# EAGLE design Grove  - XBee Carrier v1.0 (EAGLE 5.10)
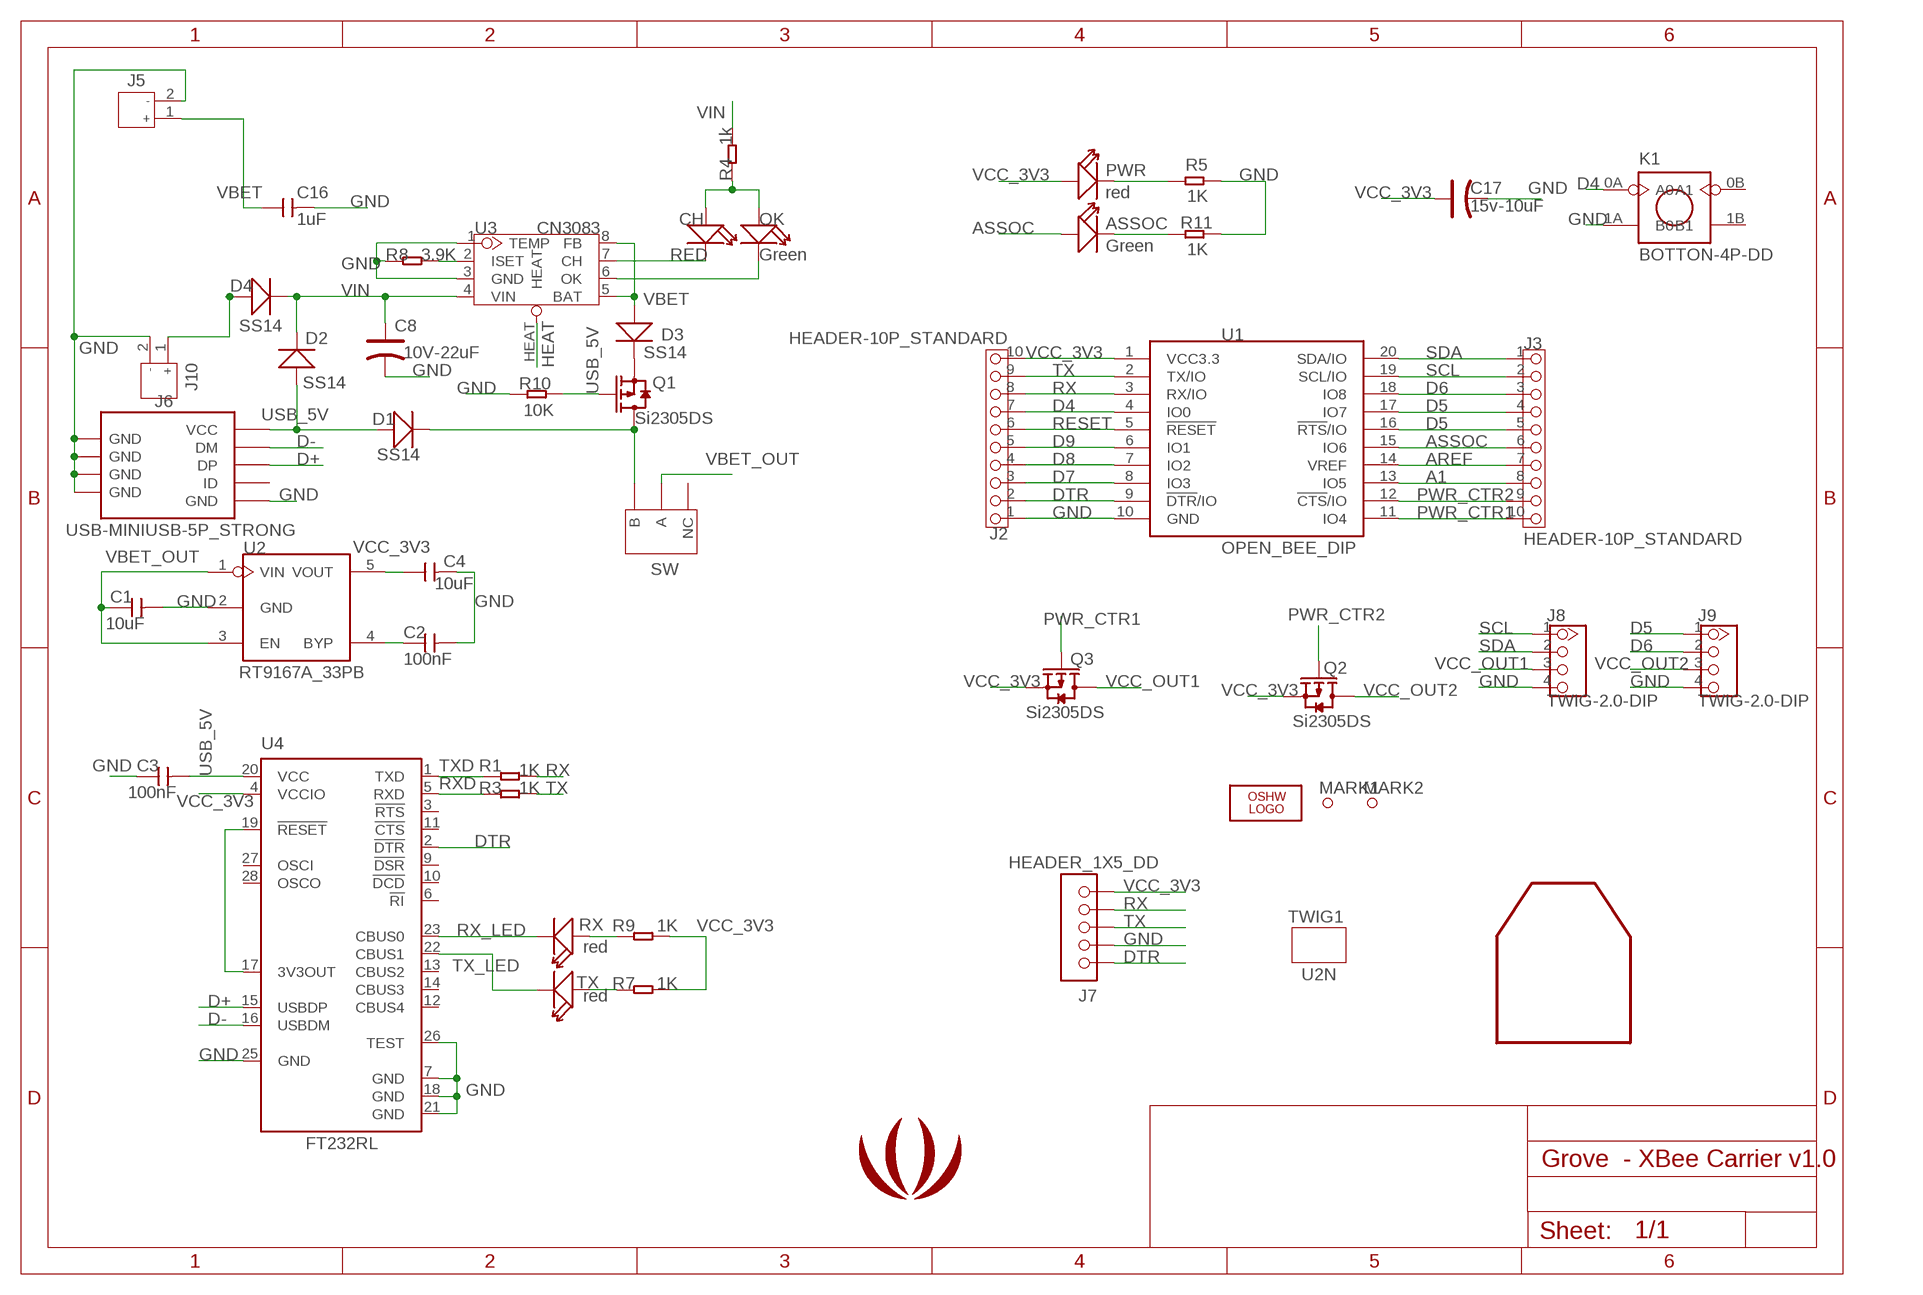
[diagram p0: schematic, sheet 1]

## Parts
ASSOC  Green  LED-0603  [D0603]
C1  10uF  C-0805  [0805]
C2  100nF  C-0603  [0603]
C3  100nF  C-0603  [0603]
C4  10uF  C-0805  [0805]
C8  10V-22uF  CAP_AVX_B  [AVX-B]
C16  1uF  C-0805  [0805]
C17  15v-10uF  CAP_AVX_A  [AVX-A]
CH  RED  LED-0603  [D0603]
D1  SS14  D-2010  [D2010]
D2  SS14  D-2010  [D2010]
D3  SS14  D-2010  [D2010]
D4  SS14  D-2010  [D2010]
J2  HEADER-10P_STANDARD  [2.54_10P]
J3  HEADER-10P_STANDARD  [2.54_10P]
J5  JST-2P-POWER-LEADED  [2P-2.0-LEADED-4.7X6.0]
J6  USB-MINIUSB-5P_STRONG  [MINI_STRONG]
J7  HEADER_1X5_DD  [CK_1X5]
J8  TWIG-2.0-DIP  [2.0_1X4]
J9  TWIG-2.0-DIP  [2.0_1X4]
J10  JST-2P-POWER-LEADED  [2P-2.0-LEADED-4.7X6.0]
K1  BOTTON-4P-DD  [BTN-S]
LOGO1  LOGO_SILK  [LOGO_SILK]
LOGO2  OSHW_LOGO_FILLX0200-NT  [OSHW_FILLX200_NOTEXT]
MARK1  PAD-MARK  [MARK]
MARK2  PAD-MARK  [MARK]
OK  Green  LED-0603  [D0603]
PWR  red  LED-0805  [D0805]
Q1  Si2305DS  010-P-MOSFETSOT23  [SOT23]
Q2  Si2305DS  010-P-MOSFETSOT23  [SOT23]
Q3  Si2305DS  010-P-MOSFETSOT23  [SOT23]
R1  1K  R-0603  [0603]
R3  1K  R-0603  [0603]
R4  1k  R-0603  [0603]
R5  1K  R-0603  [0603]
R7  1K  R-0603  [0603]
R8  3.9K  R-0603  [0603]
R9  1K  R-0603  [0603]
R10  10K  R-0603  [0603]
R11  1K  R-0603  [0603]
RX  red  LED-0603  [D0603]
SW  SWITCH-3P  [008-SW-3P-DIP]
TWIG1  U2N  [U2N_SILK]
TX  red  LED-0603  [D0603]
U1  OPEN_BEE_DIP  [CCBEE-PRO]
U2  RT9167A_33PB  RT9167A  [SOT23-5]
U3  CN3083  [SOP8]
U4  FT232RL  [SSOP28]
U$1  WIFI_SILK  [WIFI_SILK]

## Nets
A1: J3.8 U1.13(IO5)
AREF: J3.7 U1.14(VREF)
ASSOC: ASSOC.+ J3.6 U1.15(IO6)
D4: J2.7 K1.0A(A0) U1.4(IO0)
D5: J3.4 J3.5 J9.1 U1.16(!RTS!/IO) U1.17(IO7)
D6: J3.3 J9.2 U1.18(IO8)
D7: J2.3 U1.8(IO3)
D8: J2.4 U1.7(IO2)
D9: J2.5 U1.6(IO1)
D+: J6.3(DP) U4.15(USBDP)
D-: J6.2(DM) U4.16(USBDM)
DTR: J2.2 J7.1 U1.9(!DTR!/IO) U4.2(!DTR)
GND: C1.2 C2.2 C3.1 C4.2 C8.- C16.2 C17.- J2.1 J5.2 J6.5(GND) J6.GND@1(GND) J6.GND@2(GND) J6.GND@3(GND) J6.GND@4(GND) J7.2 J8.4 J9.4 J10.2 K1.1A(B0) R5.1 R8.1 R10.1 R11.1 U1.10(GND) U2.2(GND) U3.1(TEMP) U3.3(GND) U4.7(GND) U4.18(GND) U4.21(GND) U4.25(GND) U4.26(TEST)
HEAT: U3.HEAT
N$1: PWR.- R5.2
N$2: R8.2 U3.2(ISET)
N$3: D4.+ J10.1
N$6: C2.1 U2.4(BYP)
N$7: CH.- U3.7(CH)
N$8: OK.- U3.6(OK)
N$9: CH.+ OK.+ R4.1
N$10: U4.17(3V3OUT) U4.19(!RESET)
N$11: D3.- Q1.2(S)
N$12: ASSOC.- R11.2
N$13: D1.- Q1.3(D) SW.P$3(B)
N$15: R9.1 RX.+
N$16: R7.1 TX.+
PWR_CTR1: J3.10 Q3.1(G) U1.11(IO4)
PWR_CTR2: J3.9 Q2.1(G) U1.12(!CTS!/IO)
RESET: J2.6 U1.5(!RESET)
RX: J2.8 J7.4 R1.2 U1.3(RX/IO)
RX_LED: RX.- U4.23(CBUS0)
RXD: R3.1 U4.5(RXD)
SCL: J3.2 J8.1 U1.19(SCL/IO)
SDA: J3.1 J8.2 U1.20(SDA/IO)
TX: J2.9 J7.3 R3.2 U1.2(TX/IO)
TX_LED: TX.- U4.22(CBUS1)
TXD: R1.1 U4.1(TXD)
USB_5V: C3.2 D1.+ D2.+ J6.1(VCC) Q1.1(G) R10.2 U4.20(VCC)
VBET: C16.1 D3.+ J5.1 U3.5(BAT) U3.8(FB)
VBET_OUT: C1.1 SW.P$2(A) U2.1(VIN) U2.3(EN)
VCC_3V3: C4.1 C17.+ J2.10 J7.5 PWR.+ Q2.2(S) Q3.2(S) R7.2 R9.2 U1.1(VCC3.3) U2.5(VOUT) U4.4(VCCIO)
VCC_OUT1: J8.3 Q3.3(D)
VCC_OUT2: J9.3 Q2.3(D)
VIN: C8.+ D2.- D4.- R4.2 U3.4(VIN)
Unconnected: J6.4(ID) K1.0B(A1) K1.1B(B1) SW.P$1(NC) U4.3(!RTS) U4.6(!RI) U4.9(!DSR) U4.10(!DCD) U4.11(!CTS) U4.12(CBUS4) U4.13(CBUS2) U4.14(CBUS3) U4.27(OSCI) U4.28(OSCO)

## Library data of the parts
ASSOC CH OK PWR RX TX = Discrete:LED*
C1-C4 C16 = Discrete:C*: Ceramic Capacitors
C8 C17 = Discrete:CAP*: Electrolytic Capacitors,Tantalum Capacitors and Super Capacitors
D1-D4 = Discrete:D*
J2 J3 = Connector:HEADER-10P
J5 J10 = Connector:JST-2P-POWER-LEADED
J6 = Connector:USB-MINIUSB-5P
J7 = CONNECTER:HEADER_1X5
J8 J9 = Connector:TWIG-2.0-DIP
K1 = Discrete:BOTTON-4P
LOGO1 = logo:LOGO_SILK
LOGO2 = logo:OSHW_LOGO_FILL
MARK1 MARK2 = Discrete:PAD-MARK
Q1-Q3 = Discrete:010-P-MOSFET*: Si2305DS Si2323CDS
R1 R3-R5 R7-R11 = Discrete:R*
SW = Discrete:SWITCH-3P
TWIG1 = twig_template1:U2N
U1 = EXT_moudle:OPEN_BEE
U2 = IC:RT9167A: Voltage regulator
U3 = IC:CN3083
U4 = IC:FT232R: Source: http://www.ftdichip.com/Documents/DataSheets/DS_FT232R_v104.pdf
U$1 = seeedleo:WIFI_SILK

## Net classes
0 default: width 0.203 mm, drill 0.305 mm, clearance 0.127 mm

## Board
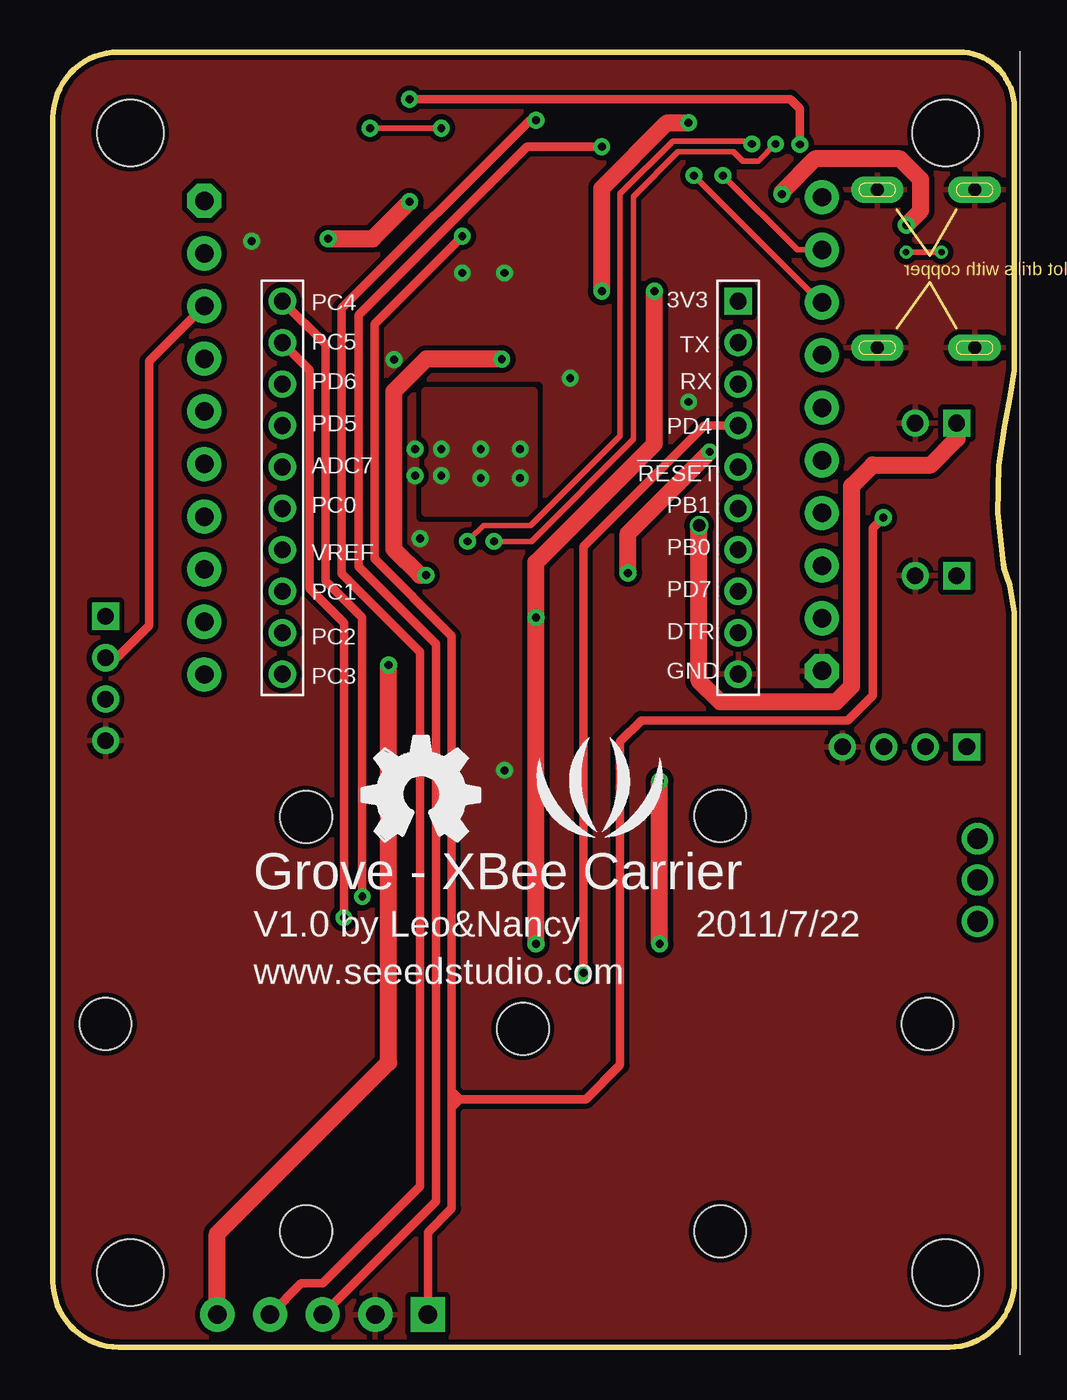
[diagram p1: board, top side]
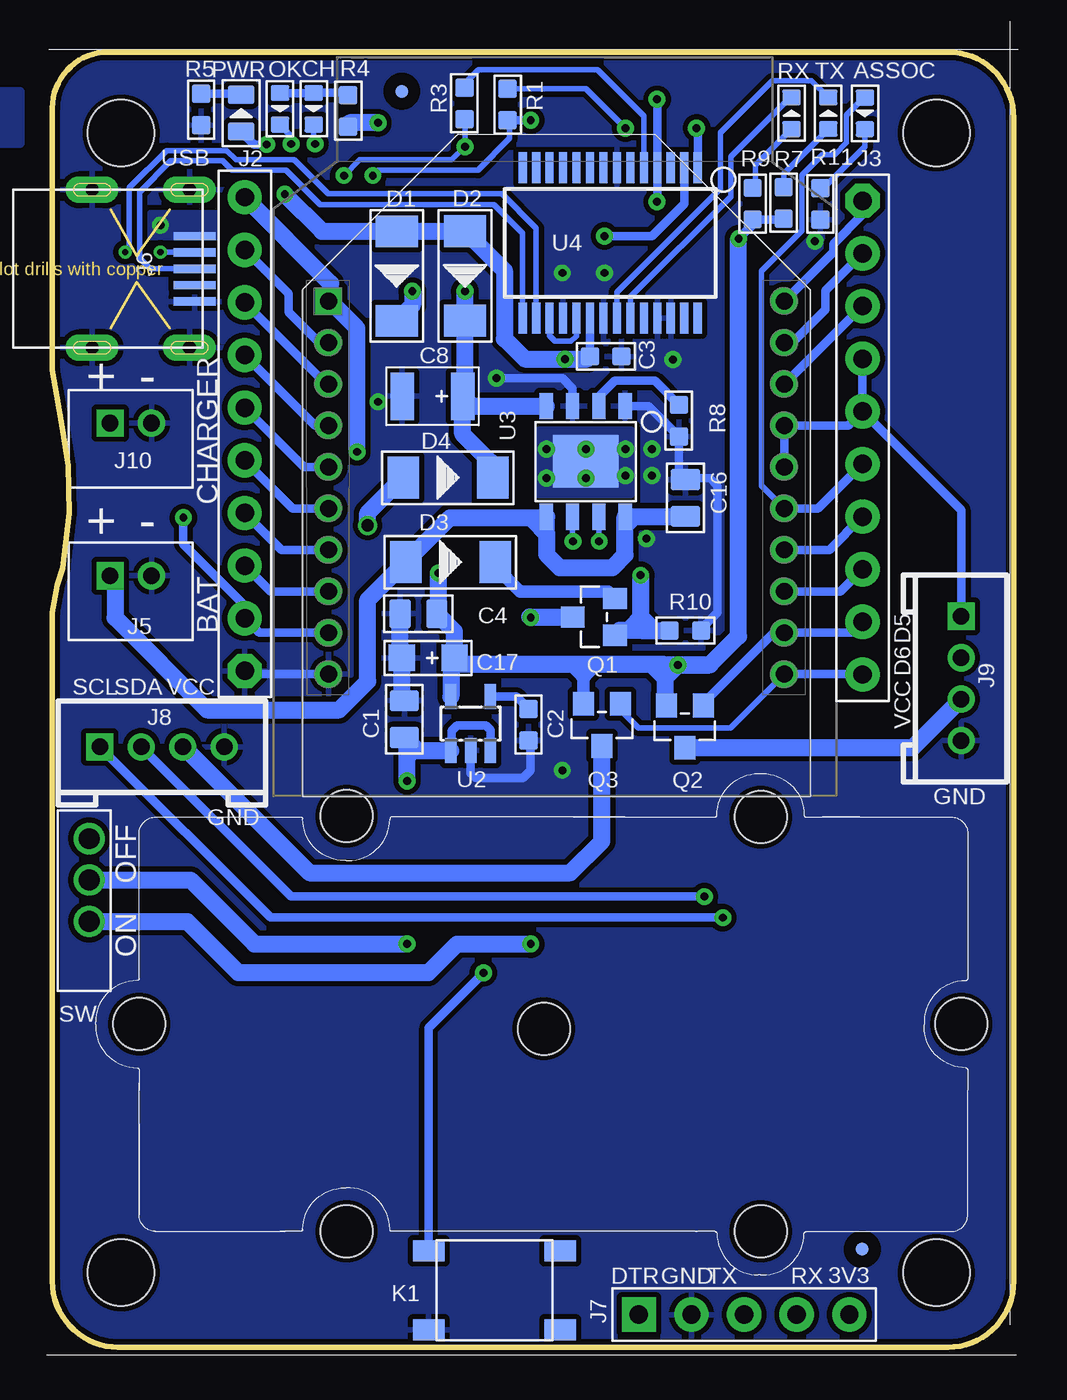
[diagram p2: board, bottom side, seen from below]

Size 46.48 x 62.53 mm. Coordinates in mm from the lower left corner, seen from the top.
Outline: 0,59.46 arc-67 2.69,62.53
Outline: 46.48,3.07 arc-67 43.79,0
Outline: 3.1,0 arc-67 0.03,2.69
Outline: 46.46,47.17 46.38,46.94
Outline: 46,38.05 46.46,35.46 46.46,3.2 arc-90 43.28,0.03 3.23,0.03 arc-90 0.06,3.2 0.06,59.35 arc-90 3.23,62.53 43.75,62.53 arc-90 46.46,59.82 46.46,47.17
Outline: 46.46,35.48 46.23,36.8 45.95,37.62 45.64,40.28 45.7,42.57 45.97,44.4 46.25,45.95 46.46,47.17
Copper layers (1*16): Top 0.035mm / dielectric 1.5mm / Bottom 0.035mm
Design rules "SeeedStudio_rule_no_angle_090911 *": minimum track width 6mil, minimum drill 12mil, track to track 6mil, track to pad 6mil, pad to pad 6mil, via to via 6mil, smd to smd 0mil, copper to edge 10mil, drill to drill 10mil, minimum pad ring 10mil, minimum via ring 6mil, stop-mask expansion 2mil, vias tented up to drill 100mil, thermal gap 10mil
Holes 3.2 mm at 3.79,58.62 3.79,3.62 43.14,3.62 43.14,58.62
Holes 2.5 mm at 2.59,15.62 32.26,25.65 12.27,25.6 22.73,15.39 32.26,5.61 42.27,15.62 12.27,5.61

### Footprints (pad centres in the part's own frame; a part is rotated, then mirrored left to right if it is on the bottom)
D0603 = smd 0.762 x 0.889: + -0.762,0; - 0.762,0
0805 = smd 1.016 x 1.397: 1 -0.889,0; 2 0.889,0
0603 = smd 0.889 x 0.889: 1 -0.762,0; 2 0.762,0
AVX-B = smd 1.143 x 2.286: + -1.46,0; - 1.46,0
AVX-A = smd 1.27 x 1.27: + -1.27,0; - 1.27,0
D2010 = smd 1.524 x 2.032: + -2.159,0; - 2.159,0
2.54_10P = drill 0.889 pad 1.651 octagon: 1 0,11.43 | drill 0.889 pad 1.651 round: 2 0,8.89; 3 0,6.35; 4 0,3.81; 5 0,1.27; 6 0,-1.27; 7 0,-3.81; 8 0,-6.35; 9 0,-8.89; 10 0,-11.43
2P-2.0-LEADED-4.7X6.0 = drill 0.8 pad 1.3 square: 1 -1,0.75 | drill 0.8 pad 1.3 round: 2 1,0.75
MINI_STRONG = smd 2.032 x 0.406: 1 0.381,-1.575; 2 0.381,-0.787; 3 0.381,0; 4 0.381,0.787; 5 0.381,1.575 | drill 0.635 pad 1.27 long: GND@1 0.635,3.81; GND@2 5.334,3.81; GND@3 5.334,-3.81; GND@4 0.635,-3.81
CK_1X5 = drill 0.889 pad 1.651 square: 1 0,5.08 | drill 0.889 pad 1.651 round: 2 0,2.54; 3 0,0; 4 0,-2.54; 5 0,-5.08
2.0_1X4 = drill 0.8 pad 1.27 square: 1 -3,0 | drill 0.8 pad 1.27 round: 2 -1,0; 3 1,0; 4 3,0
BTN-S = smd 1.524 x 1.016: 0A -3.175,1.905; 0B 3.175,1.905; 1A -3.175,-1.905; 1B 3.175,-1.905
MARK = smd 0.635 x 0.635: P$1 0,0
D0805 = smd 0.889 x 1.27: + -0.889,0; - 0.889,0
SOT23 = smd 1.016 x 1.143: 1 -0.889,-1.016; 2 0.889,-1.016; 3 0,1.016
008-SW-3P-DIP = drill 1 pad 1.5 round: P$1 -3,0.24; P$2 -1,0.24; P$3 1,0.24
CCBEE-PRO = drill 0.813 square: 1 -11,9 | drill 0.813 round: 2 -11,7; 3 -11,5; 4 -11,3; 5 -11,1; 6 -11,-1; 7 -11,-3; 8 -11,-5; 9 -11,-7; 10 -11,-9; 11 11,-9; 12 11,-7; 13 11,-5; 14 11,-3; 15 11,-1; 16 11,1; 17 11,3; 18 11,5; 19 11,7; 20 11,9
SOT23-5 = smd 0.55 x 1.2: 1 -0.95,-1.3; 2 0,-1.3; 3 0.95,-1.3; 4 0.95,1.3; 5 -0.95,1.3
SOP8 = smd 0.635 x 1.27: 1 -1.905,-2.667; 2 -0.635,-2.667; 3 0.635,-2.667; 4 1.905,-2.667; 5 1.905,2.667; 6 0.635,2.667; 7 -0.635,2.667; 8 -1.905,2.667 | smd 3.175 x 2.54: HEAT 0,0
SSOP28 = smd 0.4 x 1.5: 1 -4.225,-3.625; 2 -3.575,-3.625; 3 -2.925,-3.625; 4 -2.275,-3.625; 5 -1.625,-3.625; 6 -0.975,-3.625; 7 -0.325,-3.625; 8 0.325,-3.625; 9 0.975,-3.625; 10 1.625,-3.625; 11 2.275,-3.625; 12 2.925,-3.625; 13 3.575,-3.625; 14 4.225,-3.625; 15 4.225,3.625; 16 3.575,3.625; 17 2.925,3.625; 18 2.275,3.625; 19 1.625,3.625; 20 0.975,3.625; 21 0.325,3.625; 22 -0.325,3.625; 23 -0.975,3.625; 24 -1.625,3.625; 25 -2.275,3.625; 26 -2.925,3.625; 27 -3.575,3.625; 28 -4.225,3.625

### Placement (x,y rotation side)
ASSOC  7.24,59.56 270 bottom
C1  29.47,30.33 90 bottom
C2  23.47,30.07 270 bottom
C3  19.74,47.84 180 bottom
C4  28.79,35.42 180 bottom
C8  28.11,45.91 180 bottom
C16  15.9,41 90 bottom
C17  28.32,33.29 180 bottom
CH  33.84,59.79 270 bottom
D1  29.83,51.72 270 bottom
D2  26.54,51.72 270 bottom
D3  27.24,37.91 0 bottom
D4  27.37,41.98 0 bottom
J2  37.17,44.09 180 bottom
J3  7.36,43.91 0 bottom
J5  42.67,36.5 0 bottom
J6  39.2,52.06 180 bottom
J7  13.07,1.6 90 bottom
J8  41.16,29 0 bottom
J9  2.6,32.29 270 bottom
J10  42.67,43.87 0 bottom
K1  25.12,2.77 0 bottom
LOGO1  26.43,26.31 0 top
LOGO2  14.99,24.43 0 top
MARK1  7.37,4.75 0 bottom
MARK2  29.59,60.63 0 bottom
OK  35.47,59.78 270 bottom
PWR  37.34,59.58 90 bottom
Q1  20.32,35.27 90 bottom
Q2  15.93,29.97 180 bottom
Q3  19.93,30.05 180 bottom
R1  24.48,59.99 270 bottom
R3  26.57,60.05 270 bottom
R4  32.18,59.68 270 bottom
R5  39.27,59.75 90 bottom
R7  11.16,55.24 270 bottom
R8  16.22,44.73 90 bottom
R9  12.66,55.21 270 bottom
R10  15.91,34.61 180 bottom
R11  9.39,55.19 90 bottom
RX  10.78,59.57 90 bottom
SW  44.92,21.57 270 bottom
TWIG1  22.1,15.39 0 bottom
TX  9.01,59.57 90 bottom
U1  22.13,41.5 0 bottom
U2  26.27,30.12 0 bottom
U3  20.71,42.77 180 bottom
U4  19.53,53.31 180 bottom
U$1  22,41.17 0 bottom

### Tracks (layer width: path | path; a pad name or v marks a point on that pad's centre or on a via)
A1
  Bottom 0.406: U1.13 8.42,36.5 J3.8
AREF
  Bottom 0.406: U1.14 8.96,38.5 J3.7
ASSOC
  Bottom 0.254: ASSOC.+ 7.29,60.32 8.13,59.49 8.13,58.15 8.7,57.58 9.29,57.58 10.29,56.59 10.29,53.9 12.24,51.95 12.24,41.61 U1.15
  Bottom 0.406: U1.15 9.5,40.5 J3.6
D4  (via drill 0.38 pad 0.81)
  Top 0.406: v25.65,18.08 25.65,38.66 31.5,44.5 U1.4
  Bottom 0.406: U1.4 33.77,44.5 J2.7 | K1.0A 28.3,15.44 v25.65,18.08
D5
  Bottom 0.406: J9.1 2.6,40.42 J3.5 | U1.16 U1.17 8.04,44.5 J3.5 | J3.5 J3.4
D6
  Top 0.406: J9.2 3.15,33.29 4.7,34.85 4.7,47.61 J3.3
  Bottom 0.406: U1.18 J3.3
D7
  Bottom 0.406: U1.8 35.93,36.5 J2.3
D8
  Bottom 0.406: U1.7 35.39,38.5 J2.4
D9
  Bottom 0.406: U1.6 34.85,40.5 J2.5
D+
  Bottom 0.254: U4.15 23.76,53.78 25.15,55.17 33.53,55.17 35.18,56.82 37.79,56.82 38.24,57.27 40.74,57.27 42.24,55.77 42.24,52.57 41.74,52.07 J6.3
D-  (via drill 0.3 pad 0.64)
  Top 0.254: v42.94,52.87 v41.24,52.87
  Bottom 0.254: U4.16 23.11,54.02 24.76,55.68 33.15,55.68 34.8,57.33 37.59,57.33 38.04,57.77 40.94,57.77 42.74,55.97 42.74,53.07 v42.94,52.87 | v41.24,52.87 39.6,52.87 J6.2
DTR  (via drill 0.38 pad 0.81)
  Top 0.406: 19.3,11.61 19.3,11.99 | 19.3,11.99 19.3,12.37 | 19.3,12.37 19.3,34.34 15.57,38.07 15.57,49.4 v19.81,53.64 | 19.3,11.99 19.68,11.99 | 19.68,11.99 25.78,11.99 27.43,13.64 27.43,29.26 28.45,30.28 38.43,30.28 39.62,31.47 39.62,39.55 v40.13,40.06 | 19.68,11.99 19.3,12.37 | 19.3,11.61 19.68,11.99 | 19.3,11.61 19.3,6.73 18.15,5.58 J7.1
  Bottom 0.406: U1.9 36.47,34.5 J2.2 37.17,35.82 40.13,38.79 v40.13,40.06 | v19.81,53.64 17.53,53.64 15.96,55.21 U4.2
GND  (via drill 0.38 pad 0.81)
  Bottom 0.406: U1.10 37.01,32.5 J2.1 | U2.2 26.27,27.72 26.04,27.48 23.75,27.48 23.37,27.86 23.37,29.2 C2.2 | R10.1 15.14,34.69 14.35,35.48 14.35,41.58 14.73,41.96 15.83,41.96 C16.2 16.22,42.21 R8.1 17.68,45.43 U3.1 | U3.3 21.35,46.29 21.84,46.79 v25.02,46.79
  Bottom 0.813: C4.2 29.68,33.37 C17.- 29.59,31.34 C1.2
  other vias: 30.73,45.64 16.51,47.68 19.81,51.87 17.78,39.04 21.84,27.86 21.84,51.87 17.53,42.09 17.53,43.36 9.65,53.39
  pour Bottom: 49.91,60.63 48.01,60.63 48.01,58.09 49.91,58.09
  pour Bottom (isolate 0.254, rank 2): 46.74,62.66 -0.13,62.66 -0.13,-0.46 46.74,-0.46
  pour Top (isolate 0.254, rank 2): 46.74,62.66 -0.13,62.66 -0.13,-0.46 46.74,-0.46
HEAT  (via drill 0.38 pad 0.81)
  other vias: 22.61,43.36 22.61,41.96 20.7,43.36 18.8,43.36 18.8,42.09 20.7,41.96
  pour Bottom (isolate 0.254, no thermals): 22.99,44.25 18.54,44.25 18.54,41.2 22.99,41.2
  pour Top (isolate 0.254): 23.24,46.15 18.03,46.15 18.03,40.31 23.24,40.31
N$1
  Bottom 0.406: R5.2 37.39,60.51 PWR.-
N$2
  Bottom 0.406: U3.2 20.08,45.88 19.3,46.66 17.38,46.66 R8.2
N$3  (via drill 0.6)
  Top 0.813: v31.24,39.67 31.24,32.18 32.26,31.17 37.85,31.17 38.61,31.93 38.61,41.58 39.62,42.6 42.42,42.6 43.69,43.87 43.69,44.6 J10.1
  Bottom 0.813: v31.24,39.67 31.24,40.27 D4.+
N$6
  Bottom 0.406: U2.4 24.06,31.42 C2.1
N$7  (via drill 0.38 pad 0.81)
  Top 0.254: v20.07,38.91 20.07,39.04 20.19,39.04 20.83,39.67 23.11,39.67 27.43,43.99 27.43,55.68 29.97,58.22 33.66,58.22 v33.78,58.09
  Bottom 0.254: U3.7 20.08,38.93 v20.07,38.91 | CH.- 33.84,58.15 v33.78,58.09
N$8  (via drill 0.38 pad 0.81)
  Top 0.254: v21.34,38.91 23.14,38.91 28.07,43.84 28.07,55.55 30.23,57.71 32.89,57.71 33.35,57.25 34.09,57.25 v34.93,58.09
  Bottom 0.254: U3.6 21.35,38.93 v21.34,38.91 | OK.- 35.47,59 34.94,58.47 v34.94,58.09 v34.93,58.09
N$9
  Bottom 0.406: OK.+ CH.+ 32.28,60.55 R4.1
N$10
  Bottom 0.254: U4.19 21.16,48.82 21.42,48.56 22.19,48.56 22.46,48.83 U4.17
N$11
  Bottom 0.61: D3.- 25.09,37.71 23.88,36.5 19.64,36.5 Q1.2
N$12
  Bottom 0.254: R11.2 9.25,55.96 7.24,57.96 ASSOC.-
N$13  (via drill 0.38 pad 0.81)
  Top 0.813: v23.37,19.48 v23.37,35.23 23.37,37.9 29.08,43.61 v29.08,50.98
  Bottom 0.813: Q1.3 23.41,35.27 v23.37,35.23 | D1.- 29.08,50.31 v29.08,50.98 | SW.P$3 39.95,20.57 37.49,18.11 28.3,18.11 26.92,19.48 v23.37,19.48
N$15
  Bottom 0.254: RX.+ 12.53,57.05 12.53,56.1 R9.1
N$16
  Bottom 0.254: R7.1 11.16,56.66 TX.+
PWR_CTR1
  Bottom 0.254: Q3.1 19.04,30.77 18.16,29.9 13.73,29.9 U1.11
  Bottom 0.406: U1.11 7.37,32.5 J3.10
PWR_CTR2
  Bottom 0.406: J3.9 7.88,34.5 U1.12 11.16,34.47 11.68,34.47 15.04,31.11 Q2.1
RESET
  Bottom 0.406: U1.5 34.31,42.5 J2.6
RX  (via drill 0.38 pad 0.81)
  Top 0.254: J2.8 37.11,50.44 v30.99,56.57
  Top 0.406: v23.37,59.23 23.07,59.23 14,50.16 14,37.36 17.78,33.58 17.78,7.8 13.08,3.1 12.04,3.1 J7.4
  Bottom 0.254: v30.99,56.57 30.73,56.82 25.92,56.82 24.38,58.35 24.38,59.13 R1.2
  Bottom 0.406: U1.3 33.23,46.5 J2.8 | v23.37,59.23 R1.2
RX_LED
  Bottom 0.254: RX.- 10.83,60.38 13.72,57.48 13.72,55.55 18.56,50.71 U4.23
RXD
  Bottom 0.254: R3.1 26.57,60.99 25.89,61.66 20.14,61.66 17.91,59.43 U4.5
SCL  (via drill 0.38 pad 0.81)
  Top 0.406: v14.1,20.75 14.1,34.98 12.45,36.63 12.45,47.18 U1.19
  Bottom 0.406: U1.19 10.73,48.5 9.14,50.09 9.14,51.02 J3.2 | J8.1 35.92,20.75 v14.1,20.75
SDA  (via drill 0.38 pad 0.81)
  Top 0.406: v14.99,21.77 14.99,35.23 13.21,37.01 13.21,48.42 U1.20
  Bottom 0.406: J8.2 34.93,21.77 v14.99,21.77 | J3.1 7.36,54.67 8.76,53.26 8.76,52.86 U1.20
TX  (via drill 0.38 pad 0.81)
  Top 0.254: J2.9 35.97,52.98 v32.39,56.57
  Top 0.406: v26.54,57.96 22.93,57.96 14.8,49.83 14.8,37.7 18.54,33.96 18.54,7.07 J7.3
  Bottom 0.254: v32.39,56.57 31.62,57.33 27.18,57.33 v26.54,57.96 26.54,59.26 R3.2
  Bottom 0.406: U1.2 33.59,48.5 35.05,49.96 35.05,50.86 J2.9
TX_LED
  Bottom 0.254: TX.- 9.81,61.14 11.71,61.14 14.22,58.62 14.22,55.93 19.21,50.95 U4.22
TXD  (via drill 0.38 pad 0.81)
  Top 0.254: v18.8,58.85 v15.37,58.85
  Bottom 0.254: R1.1 20.7,60.75 v18.8,58.85
  Bottom 0.406: U4.1 15.31,58.79 v15.37,58.85
USB_5V  (via drill 0.38 pad 0.81)
  Top 0.813: v18.06,37.28 17.76,37.28 16.5,38.54 16.5,46.14 18.07,47.71 v21.72,47.71 | v35.24,55.67 35.24,55.77 36.84,57.37 40.94,57.37 41.94,56.37 41.94,54.87 v41.24,54.17
  Bottom 0.406: U4.20 C3.2
  Bottom 0.813: 18.03,34.61 19.07,34.61 Q1.1 | 18.03,34.61 R10.2 | 18.03,34.61 18.06,34.64 18.06,35.2 | v18.06,37.28 18.06,35.2 | 18.06,35.2 18.54,34.72 17.53,34.72 17.91,35.1 | C3.2 20.63,47.71 v21.72,47.71 23.66,47.71 24.64,48.69 24.64,51.98 D2.+ D1.+ 33.44,53.88 v35.24,55.67
  pour Bottom (isolate 0.254, no thermals): 41.74,53.57 38.54,53.57 38.54,54.77 41.74,54.77
VBET
  Bottom 0.813: 22.61,39.29 22.61,40.09 U3.5 22.66,40.06 23.24,40.06 | 22.61,39.29 22.61,38.28 21.97,37.64 19.43,37.64 18.81,38.26 U3.8 18.37,40.1 | D3.+ 29.65,38.15 | D3.+ 31.24,36.07 31.24,32.16 32.62,30.78 38.99,30.78 43.43,35.23 43.43,37.01 J5.1 | D3.+ 27.26,40.06 23.24,40.06 | C16.1 15.92,40.1 18.37,40.1 | 23.24,40.06 23.24,39.93 22.61,39.29 | 18.37,40.1 18.8,39.67
VBET_OUT  (via drill 0.38 pad 0.81)
  Top 0.813: v29.34,19.48 v29.34,27.36
  Bottom 0.406: U2.3 25.32,29.82 25.53,30.02 26.92,30.02 27.18,29.77 27.18,28.86 U2.1
  Bottom 0.813: U2.1 28.84,28.82 C1.1 29.34,29.31 29.34,28.5 | SW.P$2 39.79,22.57 36.7,19.48 v29.34,19.48 | v29.34,27.36 29.34,28.5 | 29.34,28.5 28.96,28.88
VCC_3V3  (via drill 0.38 pad 0.81)
  Top 0.406: v36.11,58.06 36.11,59.78 35.64,60.25 v17.27,60.25
  Top 0.813: v31.75,43.23 27.81,39.29 v27.81,37.39 | J7.5 7.99,5.5 16.26,13.77 v16.26,32.94 | v13.34,53.52 15.49,53.52 v17.27,55.3
  Bottom 0.406: v13.34,53.52 12.53,54.32 R9.2 11.21,54.45 | 11.21,54.45 11.18,54.41 | 11.2,54.45 11.07,54.45 | 11.21,54.45 11.2,54.45 | 11.2,54.45 R7.2 | v17.27,55.3 17.26,55.31 U4.4 17.26,60.23 v17.27,60.25 | v36.11,58.06 36.72,58.06 PWR.+
  Bottom 0.61: 20.82,32.41 20.82,32.83 20.95,32.97 | 20.82,32.41 Q3.2 | 20.82,32.41 20.93,32.41 21.34,32.82 | 20.82,32.41 20.73,32.41 20.32,32.82
  Bottom 0.813: 27.22,32.97 U2.5 | 27.22,32.97 27.22,33.11 C17.+ 27.05,34.57 C4.1 27.81,35.5 v27.81,37.39 | 27.22,32.97 20.95,32.97 16.89,32.97 | Q2.2 16.89,31.06 16.89,32.31 | 14.71,32.97 14.73,32.94 v16.26,32.94 16.89,32.31 | v13.34,53.52 13.34,34.34 14.71,32.97 | v31.75,43.23 31.75,49.2 33.05,50.5 U1.1 33.02,50.61 33.02,51.36 J2.10 | 16.89,32.97 14.71,32.97 | 16.89,32.31 16.89,32.97 | 16.89,32.31 17.53,32.94
VCC_OUT1
  Bottom 0.813: J8.3 40.12,29 34.04,22.91 21.46,22.91 19.94,24.43 19.94,29.03 Q3.3
VCC_OUT2
  Bottom 0.813: J9.3 4.94,28.96 Q2.3
VIN  (via drill 0.38 pad 0.81)
  Top 0.813: v26.54,50.98 26.54,55.95 29.7,59.11 v30.73,59.11
  Bottom 0.813: D4.- 25.27,42.05 25.27,42.72 26.65,44.1 C8.+ | D2.- v26.54,50.98 | D2.- | D2.- 26.54,46.02 C8.+ | U3.4 26.17,45.43 C8.+ | v30.73,59.11 32.11,59.11 32.18,59.03 R4.2

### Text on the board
tPlace: 3V3 | PC4 | PC5 | TX | PD6 | RX | PD5 | PD4 | ADC7 | RESET | PC0 | PB1 | PB0 | VREF | PD7 | PC1 | DTR | PC2 | GND | PC3 | Grove - XBee Carrier | V1.0 by Leo&Nancy | 2011/7/22 | www.seeedstudio.com
bPlace: USB | - | + | CHARGER | - | + | BAT | D5 | D6 | VCC | SDA | SCL | VCC | GND | GND | OFF | ON | 3V3 | RX | TX | GND | DTR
